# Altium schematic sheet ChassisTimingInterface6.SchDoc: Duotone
size B; Author: M. Pirello; Organization: LIGO Laboratory; Address1: California Institute of Technology; Address2: Massachusetts Institute of Technology; Address3: National Science Foundation; Address4: Australia 2086; DocumentNumber: 8; SheetNumber: 7; SheetTotal: 12; Size: B
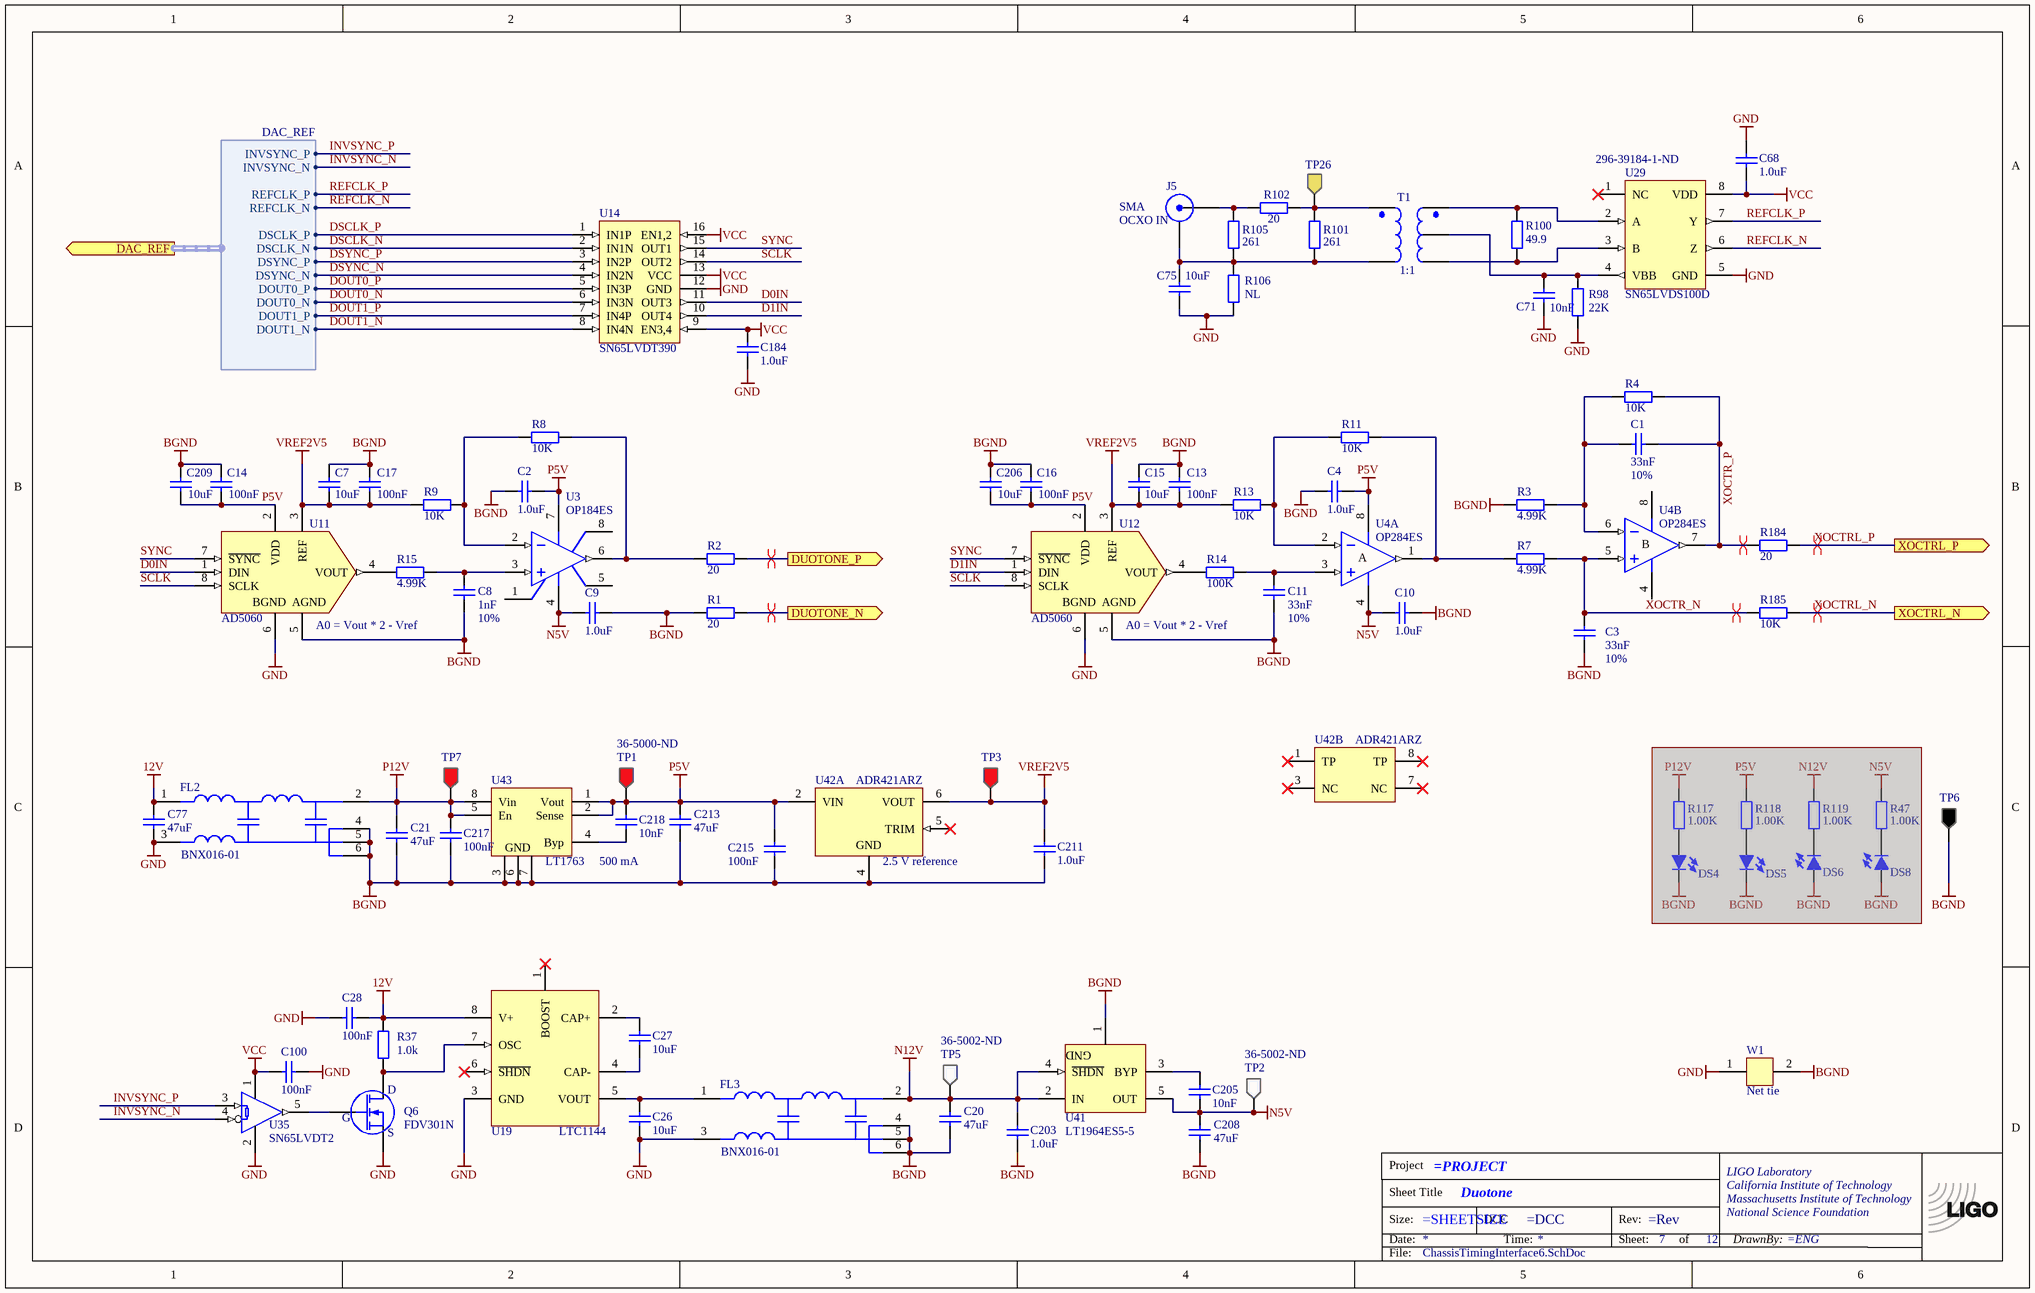
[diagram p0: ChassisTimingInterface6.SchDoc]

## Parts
*?  TitleBlock  (value not drawn)  (graphical)
?  (no value)  (no BOM)
C1  Tolerance: 10%  [CC1005-0402]  (hidden comment: 33nF)
C2  1.0uF  [CC1608-0603]
C3  Tolerance: 10%  [CC1005-0402]  (hidden comment: 33nF)
C4  1.0uF  [CC1608-0603]
C7  10uF  [CC2013-0805]
C8  Tolerance: 10%  [CC1005-0402]  (hidden comment: 1nF)
C9  1.0uF  [CC1608-0603]
C10  1.0uF  [CC1608-0603]
C11  Tolerance: 10%  [CC1005-0402]  (hidden comment: 33nF)
C13  100nF  [CC1005-0402]
C14  100nF  [CC1005-0402]
C15  10uF  [CC2013-0805]
C16  100nF  [CC1005-0402]
C17  100nF  [CC1005-0402]
C20  47uF  [CC3216-1206]
C21  47uF  [CC3216-1206]
C26  10uF  [CC2013-0805]
C27  10uF  [CC2013-0805]
C28  100nF  [CC1005-0402]
C68  1.0uF  [CC1608-0603]
C71  10nF  [CC1005-0402]
C75  10uF  [CC2013-0805]
C77  47uF  [CC3216-1206]
C100  100nF  [CC1005-0402]
C184  1.0uF  [CC1608-0603]
C203  1.0uF  [CC1608-0603]
C205  10nF  [CC1005-0402]
C206  10uF  [CC2013-0805]
C208  47uF  [CC3216-1206]
C209  10uF  [CC2013-0805]
C211  1.0uF  [CC1608-0603]
C213  47uF  [CC3216-1206]
C215  100nF  [CC1005-0402]
C217  100nF  [CC1005-0402]
C218  10nF  [CC1005-0402]
DS4  LED  [LED-0805]  (value not drawn)  (masked out: inside a compile mask, not in the netlist)
DS5  LED  [LED-0805]  (value not drawn)  (masked out: inside a compile mask, not in the netlist)
DS6  LED  [LED-0805]  (value not drawn)  (masked out: inside a compile mask, not in the netlist)
DS8  LED  [LED-0805]  (value not drawn)  (masked out: inside a compile mask, not in the netlist)
FL2  BNX016-01  [MURA-BNX016-01_V]
FL3  BNX016-01  [MURA-BNX016-01_V]
J5  SMA  [SMA-RA]
Q6  FDV301N  [SO-G3/C2.25]
R1  20  [CR1005-0402]
R2  20  [CR1005-0402]
R3  4.99K  [CR1608-0603]
R4  10K  [CR1005-0402]
R7  4.99K  [CR1608-0603]
R8  10K  [CR1005-0402]
R9  10K  [CR1005-0402]
R11  10K  [CR1005-0402]
R13  10K  [CR1005-0402]
R14  100K  [CR1005-0402]
R15  4.99K  [CR1608-0603]
R37  1.0k  [CR1608-0603]
R47  1.00K  [CR2012-0805]  (masked out: inside a compile mask, not in the netlist)
R98  22K  [CR2012-0805]
R100  49.9  [CR1608-0603]
R101  261  [CR2012-0805]
R102  20  [CR1005-0402]
R105  261  [CR2012-0805]
R106  NL  [CR2012-0805]
R117  1.00K  [CR2012-0805]  (masked out: inside a compile mask, not in the netlist)
R118  1.00K  [CR2012-0805]  (masked out: inside a compile mask, not in the netlist)
R119  1.00K  [CR2012-0805]  (masked out: inside a compile mask, not in the netlist)
R184  20  [CR1005-0402]
R185  10K  [CR1005-0402]
T1  1:1  [AT224-3]
TP1  Supplier Part Number 1: 36-5000-ND  [TP1-RED]  (hidden comment: Testpoint)
TP2  Supplier Part Number 1: 36-5002-ND  [TP1-WHT]  (hidden comment: Testpoint)
TP3  Testpoint  [TP1-RED]  (value not drawn)
TP5  Supplier Part Number 1: 36-5002-ND  [TP1-WHT]  (hidden comment: Testpoint)
TP6  Testpoint  [TP1-BLK]  (value not drawn)
TP7  Testpoint  [TP1-RED]  (value not drawn)
TP26  Testpoint  [TP1-YLW]  (value not drawn)
U3  OP184ES  [SO-8_N]
U4  OP284ES  [SO-8_N]  (parts A,B of 2)
U11  AD5060  [SSO-G8/SM8]
U12  AD5060  [SSO-G8/SM8]
U14  SN65LVDT390  [TSSOP16]
U19  LTC1144  [SO-G8]
U29  SN65LVDS100D  Supplier Part Number 1: 296-39184-1-ND  [MSOP8]
U35  SN65LVDT2  [SO-G5/E2.4]
U41  LT1964ES5-5  [LT-S5-5-TSOT-23_M]
U42  ADR421ARZ  [ADI-R-8_M]  (parts A,B of 2)
U43  LT1763  [SO-G8]
W1  Net tie  [NETTIE1_BOTH]  (net tie, no BOM)

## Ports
DAC_REF (out, harness DAC_REF), DUOTONE_N (out), DUOTONE_P (out), XOCTRL_N (out), XOCTRL_P (out)

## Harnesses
DAC_REF: DSCLK_N, DSCLK_P, DSYNC_N, DSYNC_P, DOUT0_N, DOUT0_P, DOUT1_N, DOUT1_P, REFCLK_N, REFCLK_P, INVSYNC_N, INVSYNC_P

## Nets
12V: C28.1 C77.2 FL2.1(B) R37.2 U19.8(V+)
BGND: C2.1 C3.1 C4.1 C7.2 C8.2 C9.2 C10.2 C11.1 C13.2 C14.2 C15.2 C16.2 C17.2 C20.1 C21.1 C203.1 C206.2 C208.1 C209.2 C211.1 C213.1 C215.1 C217.1 FL2.4(CG) FL2.5(CG) FL2.6(CG) FL3.4(CG) FL3.5(CG) FL3.6(CG) R1.1 R3.1 TP6.1 U11.5(AGND) U12.5(AGND) U41.1(GND) U42.4(GND) U43.3(GND) U43.6(GND) U43.7(GND) W1.2
GND: C26.1 C28.2 C68.2 C71.1 C75.1 C77.1 C100.1 C184.1 FL2.3(PSG) FL3.3(PSG) Q6.2(S) R98.2 R106.2 U11.6(BGND) U12.6(BGND) U14.12(GND) U19.3(GND) U29.5(GND) U35.2(GND) W1.1
N5V: C9.1 C10.1 C205.1 C208.2 TP2.1 U3.4(V-) U4.4(V-) U41.5(OUT)
N12V: C20.2 C203.2 FL3.2(CB) TP5.1 U41.2(IN) U41.4(~{SHDN})
P5V: C2.2 C4.2 C14.1 C16.1 C206.1 C209.1 C213.2 C215.2 C218.2 TP1.1 U3.7(V+) U4.8(V+) U11.2(VDD) U12.2(VDD) U42.2(VIN) U43.1(Vout) U43.2(Sense)
P12V: C21.2 C217.2 FL2.2(CB) TP7.1 U43.5(En) U43.8(Vin)
VCC: C68.1 C100.2 C184.2 U14.9(EN3,4) U14.13(VCC) U14.16(EN1,2) U29.8(VDD) U35.1(VCC)
VREF2V5: C7.1 C13.1 C15.1 C17.1 C211.2 R9.1 R13.1 TP3.1 U11.3(REF) U12.3(REF) U42.6(VOUT)
D0IN: U11.1(DIN) U14.11(OUT3)
D1IN: U12.1(DIN) U14.10(OUT4)
DOUT0_N: U14.6(IN3N) ; port DAC_REF.DOUT0_N
DOUT0_P: U14.5(IN3P) ; port DAC_REF.DOUT0_P
DOUT1_N: U14.8(IN4N) ; port DAC_REF.DOUT1_N
DOUT1_P: U14.7(IN4P) ; port DAC_REF.DOUT1_P
DSCLK_N: U14.2(IN1N) ; port DAC_REF.DSCLK_N
DSCLK_P: U14.1(IN1P) ; port DAC_REF.DSCLK_P
DSYNC_N: U14.4(IN2N) ; port DAC_REF.DSYNC_N
DSYNC_P: U14.3(IN2P) ; port DAC_REF.DSYNC_P
DUOTONE_N: R1.2 ; port DUOTONE_N
DUOTONE_P: R2.2 ; port DUOTONE_P
INVSYNC_N: U35.4(B) ; port DAC_REF.INVSYNC_N
INVSYNC_P: U35.3(A) ; port DAC_REF.INVSYNC_P
REFCLK_N: U29.6(Z) ; port DAC_REF.REFCLK_N
REFCLK_P: U29.7(Y) ; port DAC_REF.REFCLK_P
SCLK: U11.8(SCLK) U12.8(SCLK) U14.14(OUT2)
SYNC: U11.7(~{SYNC}) U12.7(~{SYNC}) U14.15(OUT1)
XOCTR_N: C3.2 R7.2 R185.1 U4.5(IN+)
XOCTR_P: C1.1 R4.2 R184.1 U4.7(OUT)
XOCTRL_N: R185.2 ; port XOCTRL_N
XOCTRL_P: R184.2 ; port XOCTRL_P
NetC1_2: C1.2 R3.2 R4.1 U4.6(IN-)
NetC8_1: C8.1 R15.2 U3.3(IN+)
NetC11_2: C11.2 R14.2 U4.3(IN+)
NetC26_2: C26.2 FL3.1(B) U19.5(VOUT)
NetC27_1: C27.1 U19.4(CAP-)
NetC27_2: C27.2 U19.2(CAP+)
NetC71_2: C71.2 R98.1 T1.2 U29.4(VBB)
NetC75_2: C75.2 J5.2(Y) R101.1 R105.1 R106.1 T1.4
NetC205_2: C205.2 U41.3(BYP)
NetC218_1: C218.1 U43.4(Byp)
NetJ5_1: J5.1(X) R102.2 R105.2
NetQ6_1: Q6.1(G) U35.5(R)
NetQ6_3: Q6.3(D) R37.1 U19.7(OSC)
NetR2_1: R2.1 R8.2 U3.6(OUT)
NetR7_1: R7.1 R11.2 U4.1(OUT)
NetR8_1: R8.1 R9.2 U3.2(IN-)
NetR11_1: R11.1 R13.2 U4.2(IN-)
NetR14_1: R14.1 U12.4(VOUT)
NetR15_1: R15.1 U11.4(VOUT)
NetR100_1: R100.1 T1.3 U29.3(B)
NetR100_2: R100.2 T1.1 U29.2(A)
NetR101_2: R101.2 R102.1 T1.6 TP26.1

Not connected (* = marked no-connect by the designer): U3 1(NUL) 5(NUL) 8(NC); U19 1(BOOST)* 6(~{SHDN})*; U29 1(NC)*; U42 1(TP)* 3(NC)* 5(TRIM)* 7(NC)* 8(TP)*

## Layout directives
differential pair: DUOTONE_N, DUOTONE_P, XOCTR_N, XOCTR_P, XOCTRL_N, XOCTRL_P

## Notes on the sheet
- (near J5) OCXO IN
- (near U11) A0 = Vout * 2 - Vref
- (near U12) A0 = Vout * 2 - Vref
- 500 mA
- (near U42) 2.5 V reference

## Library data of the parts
? = LIGO_logo: LIGO logo
C1 C3 C11 = ChipCap: C0402 0.033nF; Part Number: 490-13296-1-ND
C2 C4 C9 C10 C68 C184 C203 C211 = ChipCap: C0603 1.0uF; Part Number: 1276-1184-1-ND; Tolerance: 10%
C7 C15 C26 C27 C75 C206 C209 = ChipCap: C0805 10uF; Part Number: 1276-6454-1-ND; Tolerance: 10%
C8 = ChipCap: C0402 1.0nF; Part Number: 1292-1246-1-ND
C13 C14 C16 C17 C28 C100 C215 C217 = ChipCap: C0402 0.1uF; Part Number: 1276-6720-1-ND; Tolerance: 10%
C20 C21 C77 C208 C213 = ChipCap: C1206 47uF; Part Number: 490-16268-1-ND; Tolerance: 10%
C71 C205 C218 = ChipCap: C0402 0.01uF; Part Number: 311-1349-1-ND; Tolerance: 10%
DS4-DS6 DS8 = LED: Panel mount LED
FL2 FL3 = CMP-2000-05960-1: Block Type EMIFIL(R) Reference Specification, 15 A, 25 V, -40 to 125 degC, 6-Pin THD, RoHS, Bulk; Part Number: 490-5055-ND
J5 = SMA: SMA, PCB Mount, Right Angle; Part Number: 2057-RF2-49B-T-00-50-G-HDW-ND
Q6 = FDV301N: FDV301N, Digital FET, N-channel, SOT23; Part Number: FDV301NCT-ND
R1 R2 R102 R184 = ChipRes1: R0402 20; Part Number: A127156CT-ND; Tolerance: 0.1%
R3 R7 R15 = ChipRes1: R0603 4.99k; Part Number: RR08P4.99KDCT-ND; Tolerance: 0.1%
R4 R8 R9 R11 R13 R185 = ChipRes1: R0402 10k; Part Number: RR05P10.0KDCT-ND; Tolerance: 0.1%
R14 = ChipRes1: R0402 100k; Part Number: RR05P100KDCT-ND; Tolerance: 0.1%
R37 = ChipRes1: R0603 1.0k; Part Number: RR08P1.0KDCT-ND; Tolerance: 0.1%
R47 R117-R119 = ChipRes1: Resistor, surface mount; Tolerance: 1%
R98 = ChipRes1: R0805 22k; Part Number: RR12P22.0KDCT-ND; Tolerance: 0.1%
R100 = ChipRes1: R0603 49.9; Part Number: RR08Q49.9DCT-ND; Tolerance: 0.1%
R101 R105 = ChipRes1: R0805 261; Part Number: P20214CT-ND; Tolerance: 0.1%
R106 = ChipRes1: Resistor, surface mount; Tolerance: 0.1%
T1 = TC1.5-52: Transformer 1:4, wide band, 0.5-300 MHz; Part Number: TC1.5-52T
TP1 = TP_POSITIVE: Testpoint, red
TP2 TP5 = TP_NEGATIVE: Testpoint, white
TP3 TP7 = TP_POSITIVE: Testpoint, red; Part Number: 36-5000-ND
TP6 = TP_GND: Testpoint, black; Part Number: 36-5001-ND
TP26 = TP_SIGNAL: Testpoint, yellow; Part Number: 36-5004-ND
U3 = OP184ES: Precision Rail-to-Rail Input and Ouput Operational Amplifier; Part Number: OP184FSZ-REELCT-ND
U4 = OP284ES: Precision Rail-to-Rail Input and Output Operational Amplifier; Part Number: OP284ESZ-REEL7TR-ND
U11 U12 = AD5060: 16 bit DAC, 250kSPS, unipolar, serial; Part Number: AD5060BRJZ-1500RL7CT-ND
U14 = SN65LVDT390: Quad LVDS Receiver with 100 Ohm termination; Part Number: 296-6901-5-ND
U19 = LTC1144: Switched capacitor voltage inverter; Part Number: LTC1144IS8#TRPBFCT-ND
U29 = SN65LVDS100: DIFF TRANSLATOR
U35 = SN65LVDT2DBV: Single LVDS Receiver with 100 Ohm termination; Part Number: 296-6896-1-ND
U41 = CMP-0476-01338-1: 200 mA, Low Noise, Low Dropout Negative Micropower Regulator, -1.9 to -20 V Vin, -5 V Vout, 5-pin SOT23 (S5-5), -40 to 125 degC, Pb-Free, Mini Tape and Reel; Part Number: LT1964ES5-5#TRPBFCT-ND
U42 = CMP-0784-00214-1: Ultraprecision, Low Noise, XFET(R) Voltage Reference, 2.5 V Output, 4.5 to 18 V Supply, Industrial, 8-pin SOIC (R-8), Tube; Part Number: ADR421ARZ-REEL7CT-ND
U43 = LT1763: Positive voltage regulator; Part Number: LT1763CS8#PBF-ND
W1 = NetTie1: Tie two nets together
